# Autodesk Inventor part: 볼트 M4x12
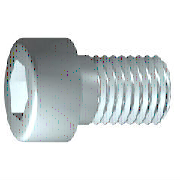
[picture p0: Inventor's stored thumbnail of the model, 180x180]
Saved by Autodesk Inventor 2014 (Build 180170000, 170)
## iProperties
IsCustomPart: 0
Created: 2012-02
Part Number: 볼트 M4x12
Material: 강철, 연강
Description: 6각머리 태핑 나사
Document SubType Name: Modeling
Standard: KS B 1003
Designer: mduedu
Standards Organization: KS
Language: ko-KR
Size Designation: M 4 x 12
Categories: <MemberInstance><Categories><Category DisplayName="조임쇠" InternalName="e4da775c-781d-43d5-af7c-5136215cf5a6" Mnemonic="FSTN"><Category DisplayName="볼트" InternalN
Density: 1 g/cm^3
Appearance: 강철
Author: mduedu
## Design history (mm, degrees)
sketch "스케치1"
  geometry: L1 (-1, 0)-(12, 0); L2 (12, 0)-(12, 2); L3 (12, 2)-(1.75, 2); L4 (1.75, 2)-(1.32, 2); L5 (1.32, 2)-(0, 2); L6 (0, 2)-(0, 3.5); L7 (0, 3.5)-(-4, 3.5); L8 (-4, 3.5)-(-4, 1.732); L9 (-4, 1.732)-(-2, 1.732); L10 (-2, 1.732)-(-1, 0); L11 (-7.2, 0)-(15.2, 0) reference; L12 (0, -0.7)-(0, 4.2) reference; L13 (1.75, 2)-(0, 2)
  constraints: 22 end point, 6 parallel, 2 collinear, 2 perpendicular, 1 horizontal, 1 point on line
  dimensions: "d1" = 10.25 distance from line of L3.end L2 (= GEL); "d2" = 0.42952 distance of L4.end L3.end (computed from GAL); "d3" = 4 distance between parallel lines of L8 L6 (= KOH); "d4" = 2 distance of L8.end L9.end (= INTI); "d5" = 60 deg angle of L10 L1; "d6" = 4 diameter of L3 L1 (= GD); "d7" = 4 diameter of L5 L1 (= BDM); "d8" = 3.4641 diameter of L9 L1 (= 1.1547 x SW); "d9" = 7 diameter of L7 L1 (= KOD); "d26" = 12 distance between parallel lines of L12 L2 (= NLG)
revolve "본체" sketch "스케치1" stored, may be unused: angle "d10" = 90 deg
sketch "스케치2"
  geometry: L1 (0, -4.9)-(0, 4.9) reference; L2 (-4.9, 0)-(4.9, 0) reference; L3 (1.732, 0)-(0.866, -1.5); L4 (0.866, -1.5)-(-0.866, -1.5); L5 (-0.866, -1.5)-(-1.732, 0); L6 (-1.732, 0)-(-0.866, 1.5); L7 (-0.866, 1.5)-(0.866, 1.5); L8 (0.866, 1.5)-(1.732, 0); 2 further points
  constraints: 12 end point, 1 coincident, 1 horizontal alignment, 1 point on line, 12 other
extrude "슬롯" join sketch "스케치2" stored distance "d11" = 10; taper "d12" = 0 deg
workplane "Work Plane1"
fillet "Fillet2" dims "d30" = 0.1 (= R)
body "Solid1"
fillet "모깎기1" dims "d17" = 0.4 (= RR)
feature "스레드" dims "d13" = 10.25 (= GEL), "d14" = 0
chamfer "모따기1" distance "d15" = 0.42941 (= -0.5 x SPD + 0.5 x GD); stored, may be unused: second distance "d16" = 0.42941 (= GUL), angle "d27" = 45 deg
other parameters: "GD" = 4 (= NND) [user parameter; used in 2 equation terms], "NLG" = 12 [user parameter; used in 1 equation term], "GEL" = 10.25 [user parameter; used in 2 equation terms], "KOD" = 7 [user parameter; used in 1 equation term], "KOH" = 4 [user parameter; used in 1 equation term], "INTI" = 2 [user parameter; used in 1 equation term], "GAL" = 0.42941 (= 0.61345 x PTC) [user parameter; used in 1 equation term], "GUL" = 0.42941 (= 0.61345 x PTC) [user parameter; used in 1 equation term], "BDM" = 4 (= NND) [user parameter; used in 1 equation term], "SW" = 3 [user parameter; used in 2 equation terms], "RR" = 0.4 [user parameter; used in 1 equation term], "SPD" = 3.14117 (= NND - 1.2269 x PTC) [user parameter; used in 1 equation term], "d19" = 0, "d28" = 0, "d29" = 0, "R" = 0.1 [user parameter; used in 1 equation term], "PHH" = 0.2 [user parameter], "GD1" = 3.14117 (= THREADDIA - 1.2269 x PTC) [user parameter], "THREADDIA" = 4 [user parameter; used in 1 equation term], "FAWI" = 45 deg [user parameter], "TPU" = 14.28571 (computed from PTC) [user parameter], "PTC" = 0.7 [user parameter; used in 5 equation terms], "NND" = 4 [user parameter; used in 3 equation terms], "TOA" = 30 deg [user parameter], "E0" = 3.465 (= 1.155 x SW) [user parameter]
